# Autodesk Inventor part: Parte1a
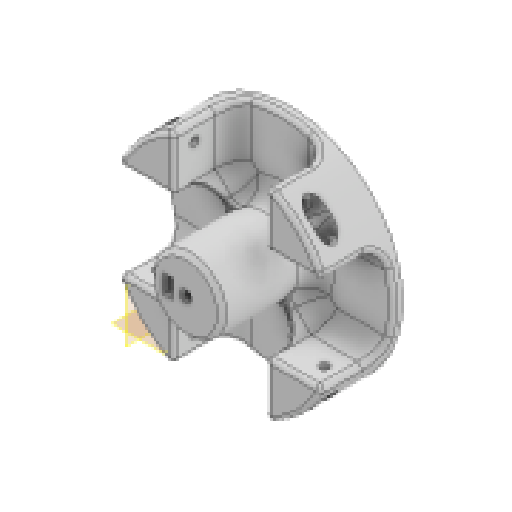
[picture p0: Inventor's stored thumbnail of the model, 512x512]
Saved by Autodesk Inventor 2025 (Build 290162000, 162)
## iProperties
Created: 2025-05
Part Number: Parte1a
Material: Generico
Document SubType Name: Modeling
Designer: R5800u
Density: 1 g/cm^3
Appearance: Default
Author: R5800u
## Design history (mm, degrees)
sketch "Schizzo1" dims "d0" = 100
  geometry: L1 (0, 0)-(35.355, 35.355); L2 (0, 0)-(50, 0); L3 (20.572, 20.572)-(20.572, 45.572); L4 (20.572, 20.572)-(45.572, 20.572); L5 (0, 0)-(0, 44.829) reference; L6 (-20.572, 20.572)-(-20.572, 45.572); L7 (0, 0)-(-35.355, 35.355); L8 (-20.572, 20.572)-(-45.572, 20.572); L9 (0, 0)-(56.569, 0); L10 (26.572, 42.355)-(26.572, 26.572); L11 (26.572, 26.572)-(42.355, 26.572); L12 (-26.572, 42.355)-(-26.572, 26.572); L13 (-26.572, 26.572)-(-42.355, 26.572); L14 (-20.572, 24.815)-(0, 4.243); L15 (0, 4.243)-(20.572, 24.815); L16 (24.815, 20.572)-(0, -4.243); L17 (0, -4.243)-(-24.815, 20.572); L18 (20.572, -20.572)-(20.572, -45.572); L19 (0, -4.243)-(20.572, -24.815); L20 (26.572, -42.355)-(26.572, -26.572); L21 (24.815, -20.572)-(0, 4.243); L22 (0, 0)-(35.355, -35.355); L23 (26.572, -26.572)-(42.355, -26.572); L24 (20.572, -20.572)-(45.572, -20.572); L25 (0, 0)-(0, -44.829); L26 (-20.572, -24.815)-(0, -4.243); L27 (0, 4.243)-(-24.815, -20.572); L28 (0, 0)-(-35.355, -35.355); L29 (-20.572, -20.572)-(-20.572, -45.572); L30 (-26.572, -42.355)-(-26.572, -26.572); L31 (-26.572, -26.572)-(-42.355, -26.572); L32 (-20.572, -20.572)-(-45.572, -20.572); 3 further points
  constraints: 64 end point, 25 symmetric about line, 13 point on line, 3 vertical, 2 coincident, 2 horizontal, 1 equal length, 9 other
  dimensions: "d1" = 45 deg angle of L2 L1; "d3" = 25 distance of L3.start L4.end; "d8" = 6 distance between parallel lines of L3 L10; "d9" = 6 distance between parallel lines of L6 L12; "d10" = 3 distance between parallel lines of L7 L14; "d11" = 3 distance between parallel lines of L1 L16; "d22" = 6 distance between parallel lines of L4 L11; "d23" = 6 distance between parallel lines of L8 L13
extrude "Estrusione1" new body sketch "Schizzo1" stored distance "d4" = 75; taper "d5" = 0 deg
node "Piano di lavoro1"
sketch "Schizzo3" dims "d24" = 100
  geometry: L1 (0, 0)-(35.355, 35.355); L2 (0, 0)-(50, 0); L3 (20.572, 20.572)-(20.572, 45.572); L4 (20.572, 20.572)-(45.572, 20.572); L5 (0, 0)-(0, 44.829); L6 (-20.572, 20.572)-(-20.572, 45.572); L7 (0, 0)-(-35.355, 35.355); L8 (-20.572, 20.572)-(-45.572, 20.572); L9 (0, 0)-(56.569, 0); L10 (26.572, 42.355)-(26.572, 26.572); L11 (26.572, 26.572)-(42.355, 26.572); L12 (-26.572, 42.355)-(-26.572, 26.572); L13 (-26.572, 26.572)-(-42.355, 26.572); L14 (-20.572, 24.815)-(0, 4.243); L15 (0, 4.243)-(20.572, 24.815); L16 (24.815, 20.572)-(0, -4.243); L17 (0, -4.243)-(-24.815, 20.572); L18 (20.572, -20.572)-(20.572, -45.572); L19 (0, -4.243)-(20.572, -24.815); L20 (26.572, -42.355)-(26.572, -26.572); L21 (24.815, -20.572)-(0, 4.243); L22 (0, 0)-(35.355, -35.355); L23 (26.572, -26.572)-(42.355, -26.572); L24 (20.572, -20.572)-(45.572, -20.572); L25 (0, 0)-(0, -44.829); L26 (-20.572, -24.815)-(0, -4.243); L27 (0, 4.243)-(-24.815, -20.572); L28 (0, 0)-(-35.355, -35.355); L29 (-20.572, -20.572)-(-20.572, -45.572); L30 (-26.572, -42.355)-(-26.572, -26.572); L31 (-26.572, -26.572)-(-42.355, -26.572); L32 (-20.572, -20.572)-(-45.572, -20.572); 16 further points
  constraints: 64 end point, 25 symmetric about line, 13 point on line, 2 coincident, 2 horizontal, 2 parallel, 2 vertical, 1 equal length, 9 other
  dimensions: "d25" = 45 deg angle of L2 L1; "d26" = 25 distance of L3.start L4.end; "d27" = 6 distance between parallel lines of L3 L10; "d28" = 6 distance between parallel lines of L6 L12; "d29" = 3 distance between parallel lines of L7 L14; "d30" = 3 distance between parallel lines of L1 L16; "d31" = 6 distance between parallel lines of L4 L11; "d32" = 6 distance between parallel lines of L8 L13; "d41" = 3 distance between parallel lines of L1 L15; "d42" = 3 distance between parallel lines of L7 L17; "d63" = 25 distance of L18.start L24.end (derived); "d64" = 25 distance of L18.start L18.end (derived); "d65" = 41.14378 distance between parallel lines of L32 L8 (derived); "d66" = 41.14378 distance between parallel lines of L24 L4 (derived); "d67" = 41.14378 distance between parallel lines of L3 L6 (derived); "d68" = 41.14378 distance between parallel lines of L18 L29 (derived)
extrude "Estrusione4" cut sketch "Schizzo3" extent not by distance; stored distance "d33" = 30; taper "d34" = 0 deg
sketch "Schizzo4"
  geometry: L1 (45.572, 37.5)-(45.572, 3) reference; L2 (45.572, 20.25)-(0, 20.25); L3 (0, 3)-(0, 37.5) reference; C1 r 2 at (37, 20.25); 2 further points
  constraints: 2 end point, 2 midpoint, 1 centre point, 1 coincident, 1 point on line
  dimensions: "d36" = 37 horizontal distance of point (0, 0) point (37, 20.25); "d37" = 4 diameter of C1
extrude "Estrusione5" cut sketch "Schizzo4" extent not by distance; stored distance "d38" = 0; taper "d39" = 0 deg
pattern_circular "Serie circolare1" dims angle "d47" = 360 deg
sketch "Schizzo5"
  geometry: C1 r 50 at (0, 0) reference; 1 further point
extrude "Estrusione6" cut sketch "Schizzo5" distance "d53" = 36; taper "d54" = 0 deg
sketch "Schizzo6"
  geometry: L1 (45.572, -20.572)-(20.572, -20.572) reference; L2 (20.572, 20.572)-(45.572, 20.572) reference; L3 (20.572, 45.572)-(20.572, 20.572) reference; L4 (-20.572, 20.572)-(-20.572, 45.572) reference; L5 (-45.572, 20.572)-(-20.572, 20.572) reference; L6 (-20.572, -20.572)-(-45.572, -20.572) reference; L7 (-20.572, -45.572)-(-20.572, -20.572) reference; L8 (20.572, -20.572)-(20.572, -45.572) reference; L9 (-20.572, 24.815)-(-24.815, 20.572); L10 (-24.815, 20.572)-(-20.572, 24.815); L11 (-24.815, -20.572)-(-20.572, -24.815); L12 (20.572, 24.815)-(24.815, 20.572); L13 (24.815, -20.572)-(20.572, -24.815); C1 r 16 at (0, 0); A1 r 50 centre (0, 0) between (45.572, 20.572) and (20.572, 45.572) reference; A2 r 50 centre (0, 0) between (-20.572, 45.572) and (-45.572, 20.572) reference; A3 r 50 centre (0, 0) between (-45.572, -20.572) and (-20.572, -45.572) reference; A4 r 50 centre (0, 0) between (20.572, -45.572) and (45.572, -20.572) reference; A5 r 35 centre (0, 53.131) between (-20.572, 24.815) and (20.572, 24.815); A6 r 35 centre (-53.131, 0) between (-24.815, -20.572) and (-24.815, 20.572); A7 r 35 centre (0, -53.131) between (20.572, -24.815) and (-20.572, -24.815); A8 r 35 centre (53.131, 0) between (24.815, 20.572) and (24.815, -20.572); 1 further point
  constraints: 10 end point, 8 point on circle, 5 centre point, 1 coincident, 1 parallel, 1 perpendicular, 17 other
  dimensions: "d55" = 32 diameter of C1; "d109" = 35 radius of A5; "d112" = 360 deg dimension on point (0, 0) A5.centre (derived)
extrude "Estrusione7" join sketch "Schizzo6" stored distance "d56" = 36; taper "d57" = 0 deg
sketch "Schizzo7"
  geometry: C1 r 2.5 at (0, 0); 1 further point
  constraints: 1 centre point, 1 coincident
  dimensions: "d69" = 5 diameter of C1
extrude "Estrusione8" cut sketch "Schizzo7" extent not by distance; stored distance "d70" = 10; taper "d71" = 0 deg
sketch "Schizzo8"
  geometry: L1 (20.572, 20.572)-(45.572, 20.572) reference; L2 (20.572, 45.572)-(20.572, 20.572) reference; L3 (-20.572, 20.572)-(-20.572, 45.572) reference; L4 (-45.572, 20.572)-(-20.572, 20.572) reference; L5 (-20.572, -20.572)-(-45.572, -20.572) reference; L6 (-20.572, -45.572)-(-20.572, -20.572) reference; L7 (20.572, -20.572)-(20.572, -45.572) reference; L8 (45.572, -20.572)-(20.572, -20.572) reference; A1 r 50 centre (0, 0) between (45.572, 20.572) and (20.572, 45.572) reference; A2 r 50 centre (0, 0) between (20.572, -45.572) and (45.572, -20.572) reference; A3 r 50 centre (0, 0) between (-45.572, -20.572) and (-20.572, -45.572) reference; A4 r 50 centre (0, 0) between (-20.572, 45.572) and (-45.572, 20.572) reference; A5 r 35 centre (0, 53.131) between (-20.572, 24.815) and (20.572, 24.815); A6 r 35 centre (-53.131, 0) between (-24.815, -20.572) and (-24.815, 20.572); A7 r 35 centre (0, -53.131) between (20.572, -24.815) and (-20.572, -24.815); A8 r 35 centre (53.131, 0) between (24.815, 20.572) and (24.815, -20.572); 9 further points
  constraints: 8 point on circle, 4 centre point, 17 other
  dimensions: "d104" = 35 radius of A5; "d107" = 360 deg dimension on point (0, 0) A5.centre (derived)
extrude "Estrusione9" cut sketch "Schizzo8" distance "d72" = 8; taper "d73" = 0 deg
node "Piano di lavoro3"
sketch "Schizzo10"
  geometry: C1 r 2 at (-17.25, 8.572) reference; C2 r 4.25 at (-17.25, 8.572); 1 further point
  constraints: 1 centre point, 1 coincident
  dimensions: "d86" = 8.5 diameter of C2
extrude "Estrusione11" cut sketch "Schizzo10" distance "d87" = 13; taper "d88" = 0 deg
node "Piano di lavoro4"
sketch "Schizzo11"
  geometry: C1 r 2 at (8.572, -17.25) reference; C2 r 4.25 at (8.572, -17.25); 1 further point
  constraints: 1 centre point, 1 coincident
  dimensions: "d90" = 8.5 diameter of C2
extrude "Estrusione12" cut sketch "Schizzo11" distance "d91" = 13; taper "d92" = 0 deg
pattern_circular "Serie circolare4" dims "d94" = 360 deg
sketch "Schizzo12"
  geometry: C1 r 2.5 at (0, 0) reference; C2 r 6 at (0, 0); 1 further point
  constraints: 1 centre point, 1 coincident
  dimensions: "d128" = 12 diameter of C2
extrude "Estrusione13" cut sketch "Schizzo12" distance "d129" = 13; taper "d130" = 0 deg
sketch "Schizzo14"
  geometry: C1 r 6 at (0, 0) reference; C2 r 16 at (0, 0) reference; C3 r 2.5 at (0, 0) reference; C4 r 20 at (0, 0); 1 further point
  constraints: 1 centre point, 1 coincident
  dimensions: "d133" = 40 diameter of C4
extrude "Estrusione14" cut sketch "Schizzo14" distance "d131" = 15; taper "d132" = 0 deg
sketch "Schizzo17"
  geometry: L1 (-45.572, -20.572)-(-20.572, -20.572) reference; L2 (-20.572, -20.572)-(-20.572, -45.572) reference; L3 (20.572, -45.572)-(20.572, -20.572) reference; L4 (20.572, -20.572)-(45.572, -20.572) reference; L5 (45.572, 20.572)-(20.572, 20.572) reference; L6 (20.572, 20.572)-(20.572, 45.572) reference; L7 (-20.572, 45.572)-(-20.572, 20.572) reference; L8 (-20.572, 20.572)-(-45.572, 20.572) reference; L9 (20.572, 20.572)-(0, 0); L10 (21.986, 20.572)-(0.707, -0.707); L11 (20.572, 21.986)-(-0.707, 0.707); C1 r 16 at (0, 0) reference; C2 r 2.5 at (0, 0) reference; A1 r 50 centre (0, 0) between (-20.572, -45.572) and (20.572, -45.572) reference; A2 r 50 centre (0, 0) between (45.572, -20.572) and (45.572, 20.572) reference; A3 r 50 centre (0, 0) between (20.572, 45.572) and (-20.572, 45.572) reference; A4 r 50 centre (0, 0) between (-45.572, 20.572) and (-45.572, -20.572) reference; 3 further points
  constraints: 6 end point, 2 parallel, 2 point on line
  dimensions: "d149" = 1 distance between parallel lines of L9 L10; "d150" = 1 distance between parallel lines of L9 L11
extrude "Estrusione16" join sketch "Schizzo17" distance "d151" = 10; taper "d152" = 0 deg
pattern_circular "Serie circolare9" dims angle "d154" = 360 deg
fillet "Raccordo32" dims "d164" = 8
fillet "Raccordo33" dims "d165" = 9.9
fillet "Raccordo34" dims "d166" = 2
fillet "Raccordo35" dims "d167" = 2
fillet "Raccordo36" dims "d168" = 1
fillet "Raccordo38" dims "d170" = 3
sketch "Schizzo18"
  geometry: C1 r 2.5 at (0, 0) reference; C2 r 16 at (0, 0); C3 r 2.5 at (0, 0); 1 further point
  constraints: 2 centre point, 2 coincident
  dimensions: "d171" = 5 diameter of C3
extrude "Estrusione17" join sketch "Schizzo18" distance "d172" = 35; taper "d173" = 0 deg
chamfer "Smusso1" distance "d174" = 2; stored, may be unused: second distance "d175" = 2, angle "d176" = 45 deg
fillet "Raccordo39" dims "d177" = 5
sketch "Schizzo19"
  geometry: L1 (-9.7, -3.6)-(-6.3, -3.6); L2 (-6.3, -3.6)-(-6.3, 3.6); L3 (-6.3, 3.6)-(-9.7, 3.6); L4 (-9.7, 3.6)-(-9.7, -3.6); L5 (-9.7, -3.6)-(-6.3, 3.6); L6 (-6.3, -3.6)-(-9.7, 3.6); 2 further points
  constraints: 12 end point, 2 midpoint, 2 parallel, 1 horizontal, 1 perpendicular
  dimensions: "d178" = 3.4 distance of L3.end L2.end; "d179" = 7.2 distance of L2.end L1.end; "d180" = 8 distance of point (0, 0) point (-8, 0)
extrude "Estrusione18" cut sketch "Schizzo19" distance "d181" = 18; taper "d182" = 0 deg
sketch "Schizzo20"
  geometry: L1 (-15.5, -3.969)-(-15.5, 3.969); A1 r 16 centre (0, 0) between (-15.5, -3.969) and (-15.5, 3.969) reference; 1 further point
  constraints: 2 end point, 2 point on circle, 1 vertical
  dimensions: "d183" = 15.5 distance from line of point (0, 0) L1
extrude "Estrusione19" cut sketch "Schizzo20" distance "d184" = 18; taper "d185" = 0 deg
sketch "Schizzo22"
  geometry: L1 (-2.1, -1.356)-(-2.1, 1.356); A1 r 2.5 centre (0, 0) between (-2.1, -1.356) and (-2.1, 1.356) reference; 1 further point
  constraints: 2 end point, 2 point on circle, 1 vertical
  dimensions: "d194" = 2.1 distance from line of point (0, 0) L1
node "Piano di lavoro5"
extrude "Estrusione20" join sketch "Schizzo22" stored distance "d195" = 0; taper "d196" = 0 deg
sketch "Schizzo21"
  geometry: L1 (-20.5, 11.578)-(-20.5, -3.641) reference; L2 (-20.5, 3.969)-(16, 3.969); L3 (16, -12.031)-(16, 19.969) reference; 4 further points
  constraints: 2 end point, 2 midpoint, 1 point on line
  dimensions: "d186" = 8 distance from line of L3 point (8, 3.969)
hole "Foro3" sketch "Schizzo21" at (8, 3.969) diameter "d197" = 4.3; stored, may be unused: countersink angle "d201" = 90 deg, drill point angle "d203" = 118 deg; dims "d198" = 6, "d199" = 4, "d200" = 2, "d202" = 8
fillet "Raccordo40" dims "d204" = 1.2
pattern_circular "Serie circolare11" dims "d206" = 90 deg
feature "ۇ耀ۉ耀ۋ耀ۍ耀ۏ耀ۑ耀ۓ耀ە耀" dims "d0" = 100, "d1" = 45 deg, "d3" = 25, "d4" = 75, "d5" = 0, "d8" = 6, "d9" = 6, "d10" = 3, "d11" = 3, "d12" = 3, "d18" = 2, "d19" = 2, "d22" = 6, "d23" = 6, "d24" = 100, "d25" = 45 deg, "d26" = 25, "d27" = 6, "d28" = 6, "d29" = 3, "d30" = 3, "d31" = 6, "d32" = 6, "d33" = 30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
node "Solido1"
node "Linea chiusa proiettata1"
node "Schizzo - Serie circolare1" dims "d107" = 360 deg (derived)
node "Linea chiusa proiettata2"
node "Schizzo - Serie circolare2" dims "d112" = 360 deg (derived)
node "Linea chiusa proiettata3"
node "Linea chiusa proiettata4"
